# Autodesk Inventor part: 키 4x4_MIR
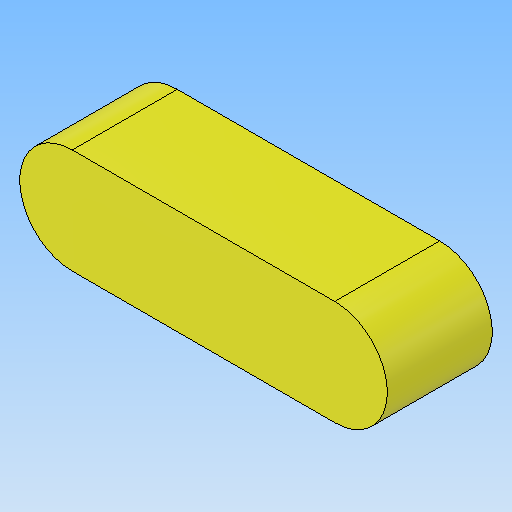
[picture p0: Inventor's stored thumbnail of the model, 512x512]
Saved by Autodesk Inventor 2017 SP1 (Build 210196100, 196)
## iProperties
Created: 2018-09
Part Number: 키 4x4_MIR
Material: 강철, 연강
Document SubType Name: Modeling
Designer: MRC
Density: 7.86 g/cm^3
Appearance: 강철
Mass: 1.65269 g
Surface Area: 2.35398 cm^2
Volume: 0.210265 cm^3
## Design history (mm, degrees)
derived "키 4x4.ipt"
  sketch "스케치1"
    geometry: L1 (5, -2)-(-5, -2) reference; L2 (-5, 2)-(5, 2) reference; A1 r 2 centre (-5, 0) between (-5, 2) and (-5, -2) reference; A2 r 2 centre (5, 0) between (5, -2) and (5, 2) reference; 2 further points
    dimensions: "d0" = 10 dimension on point (0, 0) L1.start L1.end L1 L2.start A1.centre A1 L2.end L2 A2.centre A2 point (0, -2)
feature "솔리드1::키 4x4.ipt" dims "d0" = 10
tag "피쳐 태그1"
node "솔리드1"
